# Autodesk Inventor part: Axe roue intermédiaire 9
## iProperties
Author: Flavien MARTY
Shininess: 25.0
PropertySet Name: _Private Model Information
Length Units: 11269
Angle Units: 11283
Time Units: 11279
Mass Units: 11290
Length Display Precision: 3
Angle Display Precision: 2
Compacted: True
Created: 2001-06
Part Number: Axe roue intermédiaire 9
Material: Par défaut
Document SubType Name: Modélisation
Designer: Flavien MARTY
Control State: 0
Master: False
Checked Out: False
PropertySet Name: Design Tracking Control
Density: 0.0
Volumn: 0.0
Area: 0.0
PropertySet Name: Model Information
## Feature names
1. Extrusion1
2. Extrusion3
